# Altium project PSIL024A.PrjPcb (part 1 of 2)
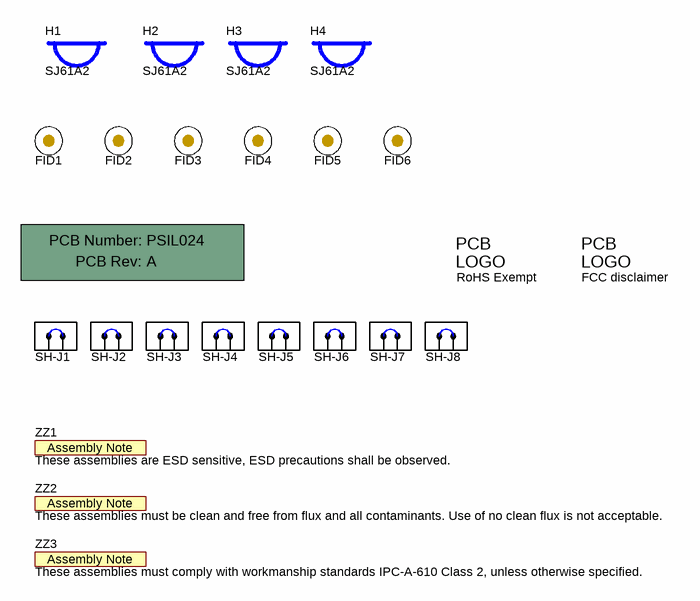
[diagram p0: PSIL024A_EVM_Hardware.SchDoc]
TID: TIDA-050023; TechSupport: http://www.ti.com/support; SCH_Rev: A; PRJ_Title: Class 6 Low Cost Flyback for PoE PD; PRJ_Number: PSIL024; PRJ_Engineer: D. Fernandez; PRJ_Customer: Public Release; PCB_Rev: A; PCB_Layout: D. Fernandez; Orderable: N/A; EVM_Orderable: N/A; CopyrightYear: 2018
4 sheets, 206 parts. Net scope: global (net labels, ports and power ports of the same name join across sheets).
Board file: PSIL024A_PCB.PcbDoc
Sheets:
  PSIL024A_EVM_Hardware.SchDoc
  PSIL024A_sch1.SchDoc
  PSIL024A_sch2.SchDoc
  PSIL024A_sch3.SchDoc

## Sheet PSIL024A_EVM_Hardware.SchDoc
size 431 x 279 mm; Date: Not shown in title block; ApprovedBy: Not shown in title block; CheckedBy: Not shown in title block; Author: Not shown in title block; CompanyName: Not shown in title block; Engineer: Not shown in title block; Organization: Not shown in title block; Address1: Not shown in title block; Address2: Not shown in title block; Address3: Not shown in title block; Address4: Not shown in title block; DocumentNumber: 1; Revision: Use project parameter SCH_Rev; SheetNumber: 4; SheetTotal: 4; PageSetup: Record=PageOptions¦CenterHorizontal=True¦CenterVertical=True¦PrintScale=1.00¦XCorrection=1.00¦YCorrection=1.00¦PrintKind=0¦BorderSize=5000000¦LeftOffset=0¦BottomOffset=0¦Orientation=2¦PaperLength=1000¦PaperWidth=1000¦Scale=100¦PaperSource=15¦PrintQuality=600¦MediaType=1¦DitherType=10¦PaperKind=Letter¦PrintScaleMode=1

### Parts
!PCB1  Printed Circuit Board  (value not drawn)  (mechanical)
FID1  Fiducial  [Fiducial10-20]  (value not drawn)
FID2  Fiducial  [Fiducial10-20]  (value not drawn)
FID3  Fiducial  [Fiducial10-20]  (value not drawn)
FID4  Fiducial  [Fiducial10-20]  (value not drawn)
FID5  Fiducial  [Fiducial10-20]  (value not drawn)
FID6  Fiducial  [Fiducial10-20]  (value not drawn)
H1  SJ61A2  [Bumpon_SJ61A2]
H2  SJ61A2  [Bumpon_SJ61A2]
H3  SJ61A2  [Bumpon_SJ61A2]
H4  SJ61A2  [Bumpon_SJ61A2]
Logo3  FCC disclaimer  [FCC_disclaimer]  (no BOM)
RoHS_Exempt  EU RoHS Exempt Logo  [EURoHS_Exempt_60mil]  (value not drawn)  (no BOM)
SH-J1  SPC02SYAN  [SPC02SYAN]  (value not drawn)
SH-J2  SPC02SYAN  [SPC02SYAN]  (value not drawn)
SH-J3  SPC02SYAN  [SPC02SYAN]  (value not drawn)
SH-J4  SPC02SYAN  [SPC02SYAN]  (value not drawn)
SH-J5  SPC02SYAN  [SPC02SYAN]  (value not drawn)
SH-J6  SPC02SYAN  [SPC02SYAN]  (value not drawn)
SH-J7  SPC02SYAN  [SPC02SYAN]  (value not drawn)
SH-J8  SPC02SYAN  [SPC02SYAN]  (value not drawn)
ZZ1  These assemblies are ESD sensitive, ESD precautions shall be observed.  [AssemblyNote]  (no BOM)
ZZ2  These assemblies must be clean and free from flux and all contaminants. Use of no clean flux is not acceptable.  [AssemblyNote]  (no BOM)
ZZ3  These assemblies must comply with workmanship standards IPC-A-610 Class 2, unless otherwise specified.  [AssemblyNote]  (no BOM)

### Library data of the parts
!PCB1 = PCB: Manufacturer: Any; PartNumber: PSIL024; SymbolCreator: a0412235
FID1-FID6 = Fiducial: Fiducial mark.  There is nothing to buy or mount.; SymbolCreator: codlsc
H1-H4 = SJ61A2: Bumpon, Hemisphere, 0.375 X 0.235, Black; Manufacturer: 3M; SymbolCreator: a0412235
Logo3 = FCC_disclaimer: SymbolCreator: codlsc
RoHS_Exempt = EURoHS_Exempt: SymbolCreator: a0412235
SH-J1-SH-J8 = SPC02SYAN: Shunt, 100mil, Flash Gold, Black; Manufacturer: Sullins Connector Solutions; Value: 1x2; Note: You can "mate" this to a header by matching the designator.  i.e. use SH-J3 for header J3; Green_Lifecycle: Active; Green_REACh: Passed
ZZ1-ZZ3 = AssemblyNote: SymbolCreator: codlsc

## Sheet PSIL024A_sch1.SchDoc
size 431 x 279 mm; Date: Not shown in title block; ApprovedBy: Not shown in title block; CheckedBy: Not shown in title block; Author: Not shown in title block; CompanyName: Not shown in title block; Engineer: Not shown in title block; Organization: Not shown in title block; Address1: Not shown in title block; Address2: Not shown in title block; Address3: Not shown in title block; Address4: Not shown in title block; DocumentNumber: 1; Revision: Use project parameter SCH_Rev; SheetNumber: 1; SheetTotal: 4; PageSetup: Record=PageOptions¦CenterHorizontal=True¦CenterVertical=True¦PrintScale=1.00¦XCorrection=1.00¦YCorrection=1.00¦PrintKind=0¦BorderSize=5000000¦LeftOffset=0¦BottomOffset=0¦Orientation=2¦PaperLength=1000¦PaperWidth=1000¦Scale=100¦PaperSource=15¦PrintQuality=600¦MediaType=1¦DitherType=10¦PaperKind=Letter¦PrintScaleMode=1
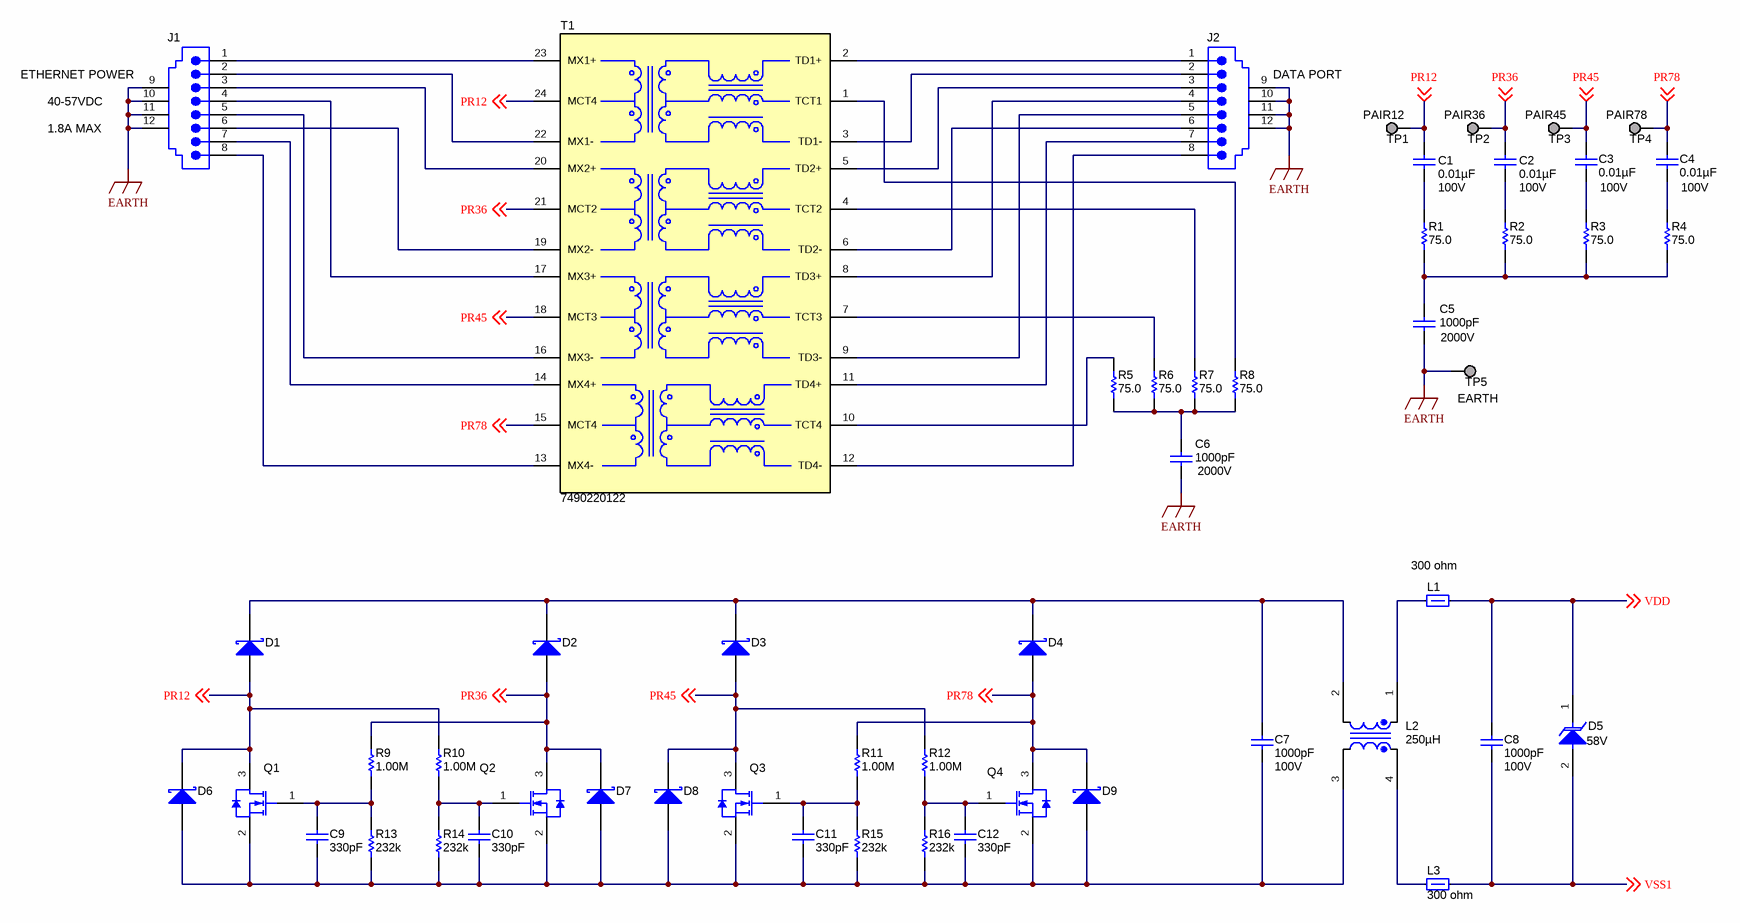
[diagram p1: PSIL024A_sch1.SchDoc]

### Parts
C1  ValueDisplayed: 0.01µF  Value2: 100V  [0603]  (hidden comment: C1608X7R2A103K)
C2  ValueDisplayed: 0.01µF  Value2: 100V  [0603]  (hidden comment: C1608X7R2A103K)
C3  ValueDisplayed: 0.01µF  Value2: 100V  [0603]  (hidden comment: C1608X7R2A103K)
C4  ValueDisplayed: 0.01µF  Value2: 100V  [0603]  (hidden comment: C1608X7R2A103K)
C5  ValueDisplayed: 1000pF  Value2: 2000V  [1808]  (hidden comment: GR442QR73D102KW01L)
C6  ValueDisplayed: 1000pF  Value2: 2000V  [1812_220]  (hidden comment: 1812GC102KAT1A)
C7  ValueDisplayed: 1000pF  Value2: 100V  [0603]  (hidden comment: C1608X7R2A102K)
C8  ValueDisplayed: 1000pF  Value2: 100V  [0603]  (hidden comment: C1608X7R2A102K)
C9  ValueDisplayed: 330pF  [0603]  (hidden comment: 885012006060)
C10  ValueDisplayed: 330pF  [0603]  (hidden comment: 885012006060)
C11  ValueDisplayed: 330pF  [0603]  (hidden comment: 885012006060)
C12  ValueDisplayed: 330pF  [0603]  (hidden comment: 885012006060)
D1  B2100-13-F  [SMB]  (value not drawn)
D2  B2100-13-F  [SMB]  (value not drawn)
D3  B2100-13-F  [SMB]  (value not drawn)
D4  B2100-13-F  [SMB]  (value not drawn)
D5  value 58V  [SMB]  (hidden comment: SMBJ58A-13-F)
D6  DNP  [SMB]  (value not drawn)
D7  DNP  [SMB]  (value not drawn)
D8  DNP  [SMB]  (value not drawn)
D9  DNP  [SMB]  (value not drawn)
J1  1-406541-1  [TEC_1-406541-1]  (value not drawn)
J2  1-406541-1  [TEC_1-406541-1]  (value not drawn)
L1  value 300 ohm  [WE-CBF_0603]
L2  ValueDisplayed: 250µH  [WE-SL5]  (hidden comment: 744272251)
L3  value 300 ohm  [WE-CBF_0603]
Q1  FDN8601  [SSOT-3]  (value not drawn)
Q2  FDN8601  [SSOT-3]  (value not drawn)
Q3  FDN8601  [SSOT-3]  (value not drawn)
Q4  FDN8601  [SSOT-3]  (value not drawn)
R1  value 75.0  [0603]  (hidden comment: CRCW060375R0FKEA)
R2  value 75.0  [0603]  (hidden comment: CRCW060375R0FKEA)
R3  value 75.0  [0603]  (hidden comment: CRCW060375R0FKEA)
R4  value 75.0  [0603]  (hidden comment: CRCW060375R0FKEA)
R5  value 75.0  [0603]  (hidden comment: CRCW060375R0FKEA)
R6  value 75.0  [0603]  (hidden comment: CRCW060375R0FKEA)
R7  value 75.0  [0603]  (hidden comment: CRCW060375R0FKEA)
R8  value 75.0  [0603]  (hidden comment: CRCW060375R0FKEA)
R9  ValueDisplayed: 1.00M  [0603]  (hidden comment: CRCW06031M00FKEA)
R10  ValueDisplayed: 1.00M  [0603]  (hidden comment: CRCW06031M00FKEA)
R11  ValueDisplayed: 1.00M  [0603]  (hidden comment: CRCW06031M00FKEA)
R12  ValueDisplayed: 1.00M  [0603]  (hidden comment: CRCW06031M00FKEA)
R13  ValueDisplayed: 232k  [0603]  (hidden comment: CRCW0603232KFKEA)
R14  ValueDisplayed: 232k  [0603]  (hidden comment: CRCW0603232KFKEA)
R15  ValueDisplayed: 232k  [0603]  (hidden comment: CRCW0603232KFKEA)
R16  ValueDisplayed: 232k  [0603]  (hidden comment: CRCW0603232KFKEA)
T1  7490220122  [Wurth_7490220122]
TP1  TESTPOINT  [Keystone_5019]  (value not drawn)
TP2  TESTPOINT  [Keystone_5019]  (value not drawn)
TP3  TESTPOINT  [Keystone_5019]  (value not drawn)
TP4  TESTPOINT  [Keystone_5019]  (value not drawn)
TP5  TESTPOINT  [Keystone_5019]  (value not drawn)

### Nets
EARTH: C5.2 C6.2 J1.9 J1.10 J1.11 J1.12 J2.9 J2.10 J2.11 J2.12 TP5.1
PR12: C1.1 D1.2(A) D6.1(K) Q1.3(D) R10.2 T1.24(MCT4) TP1.1 ; off-sheet PR12
PR36: C2.1 D2.2(A) D7.1(K) Q2.3(D) R9.2 T1.21(MCT2) TP2.1 ; off-sheet PR36
PR45: C3.1 D3.2(A) D8.1(K) Q3.3(D) R12.2 T1.18(MCT3) TP3.1 ; off-sheet PR45
PR78: C4.1 D4.2(A) D9.1(K) Q4.3(D) R11.2 T1.15(MCT4) TP4.1 ; off-sheet PR78
VDD: C8.1 D5.1(K) L1.2 ; off-sheet VDD
VSS1: C8.2 D5.2(A) L3.2 ; off-sheet VSS1
NetC1_2: C1.2 R1.2
NetC2_2: C2.2 R2.2
NetC3_2: C3.2 R3.2
NetC4_2: C4.2 R4.2
NetC5_1: C5.1 R1.1 R2.1 R3.1 R4.1
NetC6_1: C6.1 R5.2 R6.2 R7.2 R8.2
NetC7_1: C7.1 D1.1(K) D2.1(K) D3.1(K) D4.1(K) L2.2
NetC7_2: C7.2 C9.2 C10.2 C11.2 C12.2 D6.2(A) D7.2(A) D8.2(A) D9.2(A) L2.3 Q1.2(S) Q2.2(S) Q3.2(S) Q4.2(S) R13.1 R14.1 R15.1 R16.1
NetC9_1: C9.1 Q1.1(G) R9.1 R13.2
NetC10_1: C10.1 Q2.1(G) R10.1 R14.2
NetC11_1: C11.1 Q3.1(G) R11.1 R15.2
NetC12_1: C12.1 Q4.1(G) R12.1 R16.2
NetJ1_1: J1.1 T1.23(MX1+)
NetJ1_2: J1.2 T1.22(MX1-)
NetJ1_3: J1.3 T1.20(MX2+)
NetJ1_4: J1.4 T1.17(MX3+)
NetJ1_5: J1.5 T1.16(MX3-)
NetJ1_6: J1.6 T1.19(MX2-)
NetJ1_7: J1.7 T1.14(MX4+)
NetJ1_8: J1.8 T1.13(MX4-)
NetJ2_1: J2.1 T1.2(TD1+)
NetJ2_2: J2.2 T1.3(TD1-)
NetJ2_3: J2.3 T1.5(TD2+)
NetJ2_4: J2.4 T1.8(TD3+)
NetJ2_5: J2.5 T1.9(TD3-)
NetJ2_6: J2.6 T1.6(TD2-)
NetJ2_7: J2.7 T1.11(TD4+)
NetJ2_8: J2.8 T1.12(TD4-)
NetL1_1: L1.1 L2.1
NetL2_4: L2.4 L3.1
NetR5_1: R5.1 T1.10(TCT4)
NetR6_1: R6.1 T1.7(TCT3)
NetR7_1: R7.1 T1.4(TCT2)
NetR8_1: R8.1 T1.1(TCT1)

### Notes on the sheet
- ETHERNET POWER
- (near J2) DATA PORT
- 40-57VDC
- 1.8A MAX
- (near TP1) PAIR12
- (near TP2) PAIR36
- (near TP3) PAIR45
- (near TP4) PAIR78
- (near TP5) EARTH

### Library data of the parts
C1-C4 = C1608X7R2A103K: CAP, CERM, 0.01uF, 100V, +/-10%, X7R, 0603; Manufacturer: TDK; Polarized: N; CompType: Capacitor; U/M: EA; Cap_F: 0.00000001; Tolerance_%: 10; ESR_Ohm: 0.0661; Value1: 0.0661 ohm; VDC_V: 100; TaMin_C: -55; TaMax_C: 125
C5 = GR442QR73D102KW01L: CAP, CERM, 1000 pF, 2000 V, +/- 10%, X7R, 1808; Manufacturer: MuRata; Polarized: N; CompType: Capacitor; Value: 1000pF; U/M: EA; Cap_F: 0.000000001; Tolerance_%: 10; Value1: Unknown; VDC_V: 2000; TaMin_C: -55; TaMax_C: 125; AEC Category: Q200; SizeArea_mm2: 9; SizeAreaWB_mm2: 16.5; SizeX_mm: 4.5; SizeY_mm: 2; SizeZ_mm: 2.03
C6 = 1812GC102KAT1A: CAP, CERM, 1000 pF, 2000 V,+/- 10%, X7R, 1812; Manufacturer: AVX; Polarized: N; CompType: Capacitor; Value: 1000pF; U/M: EA; Cap_F: 0.000000001; Tolerance_%: 10; Value1: Unknown; VDC_V: 2000; TaMin_C: -55; TaMax_C: 125; Cap_Case: 1812; AEC Category: Q200; SizeArea_mm2: 14.4; SizeAreaWB_mm2: 23.1; SizeX_mm: 4.5; SizeY_mm: 3.2; SizeZ_mm: 2.2
C7 C8 = C1608X7R2A102K: CAP, CERM, 1000pF, 100V, +/-10%, X7R, 0603; Manufacturer: TDK; Polarized: N; CompType: Capacitor; U/M: EA; Cap_F: 0.000000001; Tolerance_%: 10; ESR_Ohm: 0.2494; Value1: 0.2494 ohm; VDC_V: 100; TaMin_C: -55; TaMax_C: 125
C9-C12 = 885012006060: CAP, CERM, 330 pF, 50 V, +/- 5%, C0G/NP0, 0603; Manufacturer: Wurth Elektronik; Polarized: N; CompType: Capacitor; Value: 330pF; U/M: EA; Cap_F: 0.00000000033; Tolerance_%: 5; Value1: Unknown; VDC_V: 50; Value2: 50V; TaMin_C: -55; TaMax_C: 125; AEC Category: Q200
D1-D4 D6-D9 = B2100-13-F: Diode, Schottky, 100 V, 2 A, SMB; Manufacturer: Diodes Inc.; Value: 100V; U/M: EA; Vf_V: 0.79; Value1: 2A; Value2: 0.79V; Io_A: 2; Vr_V: 100; TJmax_C: 150; RJC_CperW: 15; AEC Category: Q101
D5 = SMBJ58A-13-F: Diode, TVS, Uni, 58V, 600W, SMB; Manufacturer: Diodes Inc.; U/M: EA; Power_W: 5; Vr_V: 58; Value1: 5W
J1 J2 = 1-406541-1: RJ-45, No LED, tab up, R/A, TH; Manufacturer: TE Connectivity; SymbolCreator: x0208326; CompType: Connector; ContactFinish: Gold
L1 L3 = 742792641: Ferrite Bead, 300 ohm @ 100 MHz, 2 A, 0603; Manufacturer: Wurth Elektronik; Imax_A: 2; DCR_ohm: 0.15; Value1: 0.15 ohm; Value2: 2A; ZTyp@100MHz_Ohm: 300
L2 = 744272251: Coupled inductor, 250 µH,  A, 0.035 ohm, SMD; Manufacturer: Wurth Elektronik; SymbolCreator: a0412235; Value: 250uH; Ind_H: 250.0E-6; DCR_ohm: 0.035
Q1-Q4 = FDN8601: MOSFET, N-CH, 100V, 2.7A, SSOT-3; Manufacturer: Fairchild Semiconductor; Alternate Manufacturer: None; U/M: EA; ChType: N; VdsMax_V: 100; Value1: ? ohm; Rdson45_Ohm: 0; Value2: 3 nC; QgTyp_nC: 3; Vgs_V: 20; IdsMax_A: 2.7
R1-R8 = CRCW060375R0FKEA: RES, 75.0 ohm, 1%, 0.1W, 0603; Manufacturer: Vishay-Dale; CompType: Resistor; Res_ohm: 75; Value_Code: 75R0; Tolerance_%: 1; Power_W: 0.1; TempCo: 100 ppm/C; EIA_Code: E96; U/M: EA
R9-R12 = CRCW06031M00FKEA: RES, 1.00 M, 1%, 0.1 W, 0603; Manufacturer: Vishay-Dale; CompType: Resistor; Value: 1.00Meg; Res_ohm: 1000000; Value_Code: 1M00; Tolerance_%: 1; Power_W: 0.1; Value2: 0.1W; VDC_V: 75; TempCo: 100 ppm/C; EIA_Code: E96; U/M: EA; AEC Category: Q200
R13-R16 = CRCW0603232KFKEA: RES, 232 k, 1%, 0.1 W, 0603; Manufacturer: Vishay-Dale; CompType: Resistor; Value: 232k; Res_ohm: 232000; Tolerance_%: 1; Power_W: 0.1; Value2: 0.1W; VDC_V: 75; TempCo: 100 ppm/C; EIA_Code: E96; U/M: EA; AEC Category: Q200
T1 = 7490220122: Transformer, 350 uH, SMT; Manufacturer: Wurth Elektronik; SymbolCreator: Altium; Value: 350 uH; U/M: EA
TP1-TP5 = 5019: Test Point, Miniature, SMT; Manufacturer: Keystone; CompType: Test Point Loop; U/M: EA

## Sheet PSIL024A_sch2.SchDoc
size 431 x 279 mm; Date: Not shown in title block; ApprovedBy: Not shown in title block; CheckedBy: Not shown in title block; Author: Not shown in title block; CompanyName: Not shown in title block; Engineer: Not shown in title block; Organization: Not shown in title block; Address1: Not shown in title block; Address2: Not shown in title block; Address3: Not shown in title block; Address4: Not shown in title block; DocumentNumber: 1; Revision: Use project parameter SCH_Rev; SheetNumber: 2; SheetTotal: 4; PageSetup: Record=PageOptions¦CenterHorizontal=True¦CenterVertical=True¦PrintScale=1.00¦XCorrection=1.00¦YCorrection=1.00¦PrintKind=0¦BorderSize=5000000¦LeftOffset=0¦BottomOffset=0¦Orientation=2¦PaperLength=1000¦PaperWidth=1000¦Scale=100¦PaperSource=15¦PrintQuality=600¦MediaType=1¦DitherType=10¦PaperKind=Letter¦PrintScaleMode=1
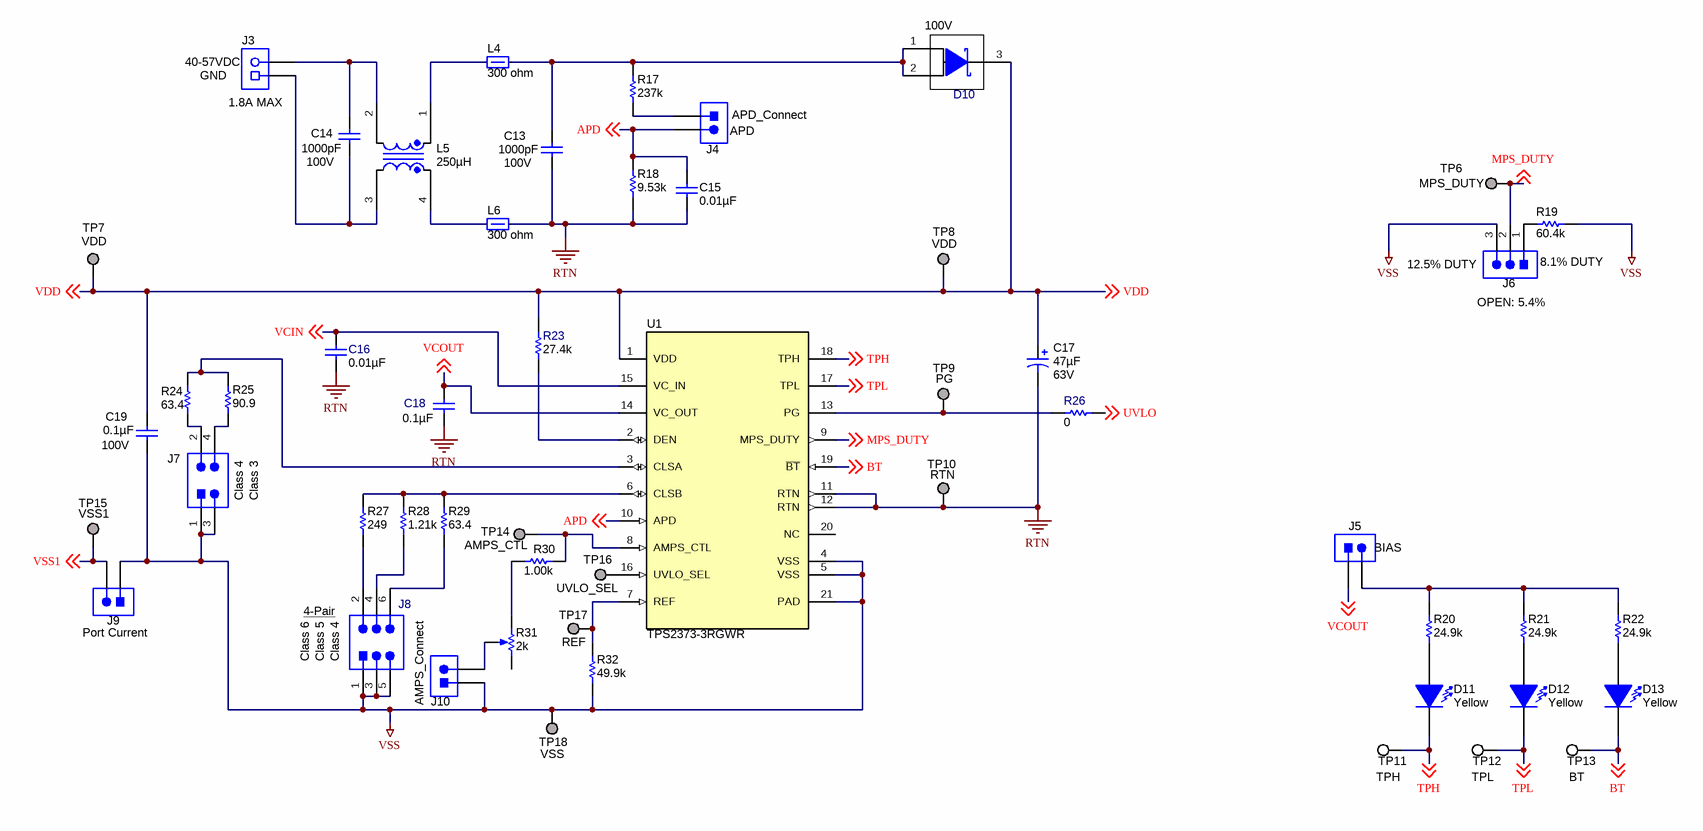
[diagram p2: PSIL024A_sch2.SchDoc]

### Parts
C13  ValueDisplayed: 1000pF  Value2: 100V  [0603L]  (hidden comment: C1608X7R2A102K)
C14  ValueDisplayed: 1000pF  Value2: 100V  [0603L]  (hidden comment: C1608X7R2A102K)
C15  ValueDisplayed: 0.01µF  [0603L]  (hidden comment: C1608X7R1H103K)
C16  ValueDisplayed: 0.01µF  [0603]  (hidden comment: GRM188R61H103KA01D)
C17  ValueDisplayed: 47µF  Value2: 63V  [SM_RADIAL_F]  (hidden comment: EEE-FK1J470P)
C18  ValueDisplayed: 0.1µF  [0603]  (hidden comment: 06033D104KAT2A)
C19  ValueDisplayed: 0.1µF  Value2: 100V  [0805_HV]  (hidden comment: C0805C104K1RACTU)
D10  100V  [PowerDI5]
D11  Yellow  [WL-SMCW_YELLOW]
D12  Yellow  [WL-SMCW_YELLOW]
D13  Yellow  [WL-SMCW_YELLOW]
J3  39357-0002  [Molex_39357-0002]  (value not drawn)
J4  87898-0204  [Molex_87898-0204]  (value not drawn)
J5  87898-0204  [Molex_87898-0204]  (value not drawn)
J6  TSM-103-01-L-SV  [Samtec_TSM-103-01-X-SV]  (value not drawn)
J7  15-91-2040  [Molex_15-91-2040]  (value not drawn)
J8  TSM-103-01-L-DV  [Samtec_TSM-103-01-x-DV]  (value not drawn)
J9  Port Current  [Molex_87898-0204]
J10  AMPS_Connect  [Molex_87898-0204]
L4  value 300 ohm  [WE-CBF_0603]
L5  ValueDisplayed: 250µH  [WE-SL5]  (hidden comment: 744272251)
L6  value 300 ohm  [WE-CBF_0603]
R17  value 237k  [0603L]  (hidden comment: CRCW0603237KFKEA)
R18  ValueDisplayed: 9.53k  [0603]  (hidden comment: CRCW06039K53FKEA)
R19  ValueDisplayed: 60.4k  [0603]  (hidden comment: CRCW060360K4FKEA)
R20  ValueDisplayed: 24.9k  [0603]  (hidden comment: CRCW060324K9FKEA)
R21  ValueDisplayed: 24.9k  [0603]  (hidden comment: CRCW060324K9FKEA)
R22  ValueDisplayed: 24.9k  [0603]  (hidden comment: CRCW060324K9FKEA)
R23  ValueDisplayed: 27.4k  [0603]  (hidden comment: RC0603FR-0727K4L)
R24  value 63.4  [0603]  (hidden comment: CRCW060363R4FKEA)
R25  ValueDisplayed: 90.9  [0603]  (hidden comment: CRCW060390R9FKEA)
R26  ValueDisplayed: 0  [0603L]  (hidden comment: CRCW06030000Z0EA)
R27  ValueDisplayed: 249  [0603]  (hidden comment: CRCW0603249RFKEA)
R28  ValueDisplayed: 1.21k  [0603]  (hidden comment: CRCW06031K21FKEA)
R29  value 63.4  [0603]  (hidden comment: CRCW060363R4FKEA)
R30  ValueDisplayed: 1.00k  [2010]  (hidden comment: CRCW20101K00FKEF)
R31  value 2k  [BOURNS_3386P]  (hidden comment: 3386P-1-202LF)
R32  ValueDisplayed: 49.9k  [0603]  (hidden comment: CRCW060349K9FKEA)
TP6  TESTPOINT  [Keystone_5019]  (value not drawn)
TP7  VDD  [Keystone_5019]
TP8  VDD  [Keystone_5019]
TP9  PG  [Keystone_5019]
TP10  RTN  [Keystone_5019]
TP11  5015  [Testpoint_Keystone_Miniature]  (value not drawn)
TP12  5015  [Testpoint_Keystone_Miniature]  (value not drawn)
TP13  5015  [Testpoint_Keystone_Miniature]  (value not drawn)
TP14  AMPS_CTL  [Keystone_5019]
TP15  VSS1  [Keystone_5019]
TP16  UVLO_SEL  [Keystone_5019]
TP17  REF  [Keystone_5019]
TP18  VSS  [Keystone_5019]
U1  TPS2373-3RGWR  [RGW0020B]

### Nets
RTN: C13.2 C15.1 C16.2 C17.2(-) C18.2 L6.2 R18.1 TP10.1 U1.11(RTN) U1.12(RTN)
VSS: C19.2 J6.3 J7.1 J7.3 J8.1 J8.3 J8.5 J9.1 J10.1 R19.2 R32.2 TP18.1 U1.4(VSS) U1.5(VSS) U1.21(PAD)
APD: C15.2 J4.2 R18.2 U1.10(APD) ; off-sheet APD
BT: D13.1(K) TP13.1 U1.19(~{BT}) ; off-sheet BT
MPS_DUTY: J6.2 TP6.1 U1.9(MPS_DUTY) ; off-sheet MPS_DUTY
TPH: D11.1(K) TP11.1 U1.18(TPH) ; off-sheet TPH
TPL: D12.1(K) TP12.1 U1.17(TPL) ; off-sheet TPL
UVLO: R26.2 ; off-sheet UVLO
VCIN: C16.1 U1.15(VC_IN) ; off-sheet VCIN
VCOUT: C18.1 J5.1 U1.14(VC_OUT) ; off-sheet VCOUT
VDD: C17.1(+) C19.1 D10.3(K) R23.2 TP7.1 TP8.1 U1.1(VDD) ; off-sheet VDD
VSS1: J9.2 TP15.1 ; off-sheet VSS1
NetC13_1: C13.1 D10.1(A) D10.2(A) L4.2 R17.2
NetC14_1: C14.1 J3.2 L5.2
NetC14_2: C14.2 J3.1 L5.3
NetD11_2: D11.2(A) R20.1
NetD12_2: D12.2(A) R21.1
NetD13_2: D13.2(A) R22.1
NetJ4_1: J4.1 R17.1
NetJ5_2: J5.2 R20.2 R21.2 R22.2
NetJ6_1: J6.1 R19.1
NetJ7_2: J7.2 R24.1
NetJ7_4: J7.4 R25.1
NetJ8_2: J8.2 R27.1
NetJ8_4: J8.4 R28.1
NetJ8_6: J8.6 R29.1
NetJ10_2: J10.2 R31.2(WIPER)
NetL4_1: L4.1 L5.1
NetL5_4: L5.4 L6.1
NetR23_1: R23.1 U1.2(DEN)
NetR24_2: R24.2 R25.2 U1.3(CLSA)
NetR26_1: R26.1 TP9.1 U1.13(PG)
NetR27_2: R27.2 R28.2 R29.2 U1.6(CLSB)
NetR30_1: R30.1 R31.1(CCW)
NetR30_2: R30.2 TP14.1 U1.8(AMPS_CTL)
NetR32_1: R32.1 TP17.1 U1.7(REF)
NetTP16_1: TP16.1 U1.16(UVLO_SEL)

Not connected (* = marked no-connect by the designer): R31 3(CW); U1 20(NC)

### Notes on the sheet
- (near J3) GND
- (near J3) 1.8A MAX
- (near J3) 40-57VDC
- (near J4) APD
- (near J4) APD_Connect
- (near TP6) MPS_DUTY
- (near J6) 12.5% DUTY
- (near J6) OPEN: 5.4%
- 8.1% DUTY
- (near J7) Class 4
- Class 3
- (near J5) BIAS
- (near J8) Class 6
- (near J8) Class 5
- (near J8) 4-Pair
- (near J8) Class 4
- (near TP11) TPH
- (near TP12) TPL
- (near TP13) BT

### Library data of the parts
C13 C14 = C1608X7R2A102K: CAP, CERM, 1000pF, 100V, +/-10%, X7R, 0603; Manufacturer: TDK; Polarized: N; CompType: Capacitor; U/M: EA; Cap_F: 0.000000001; Tolerance_%: 10; ESR_Ohm: 0.2494; Value1: 0.2494 ohm; VDC_V: 100; TaMin_C: -55; TaMax_C: 125; Cap_Case: 0603
C15 = C1608X7R1H103K: CAP, CERM, 0.01uF, 50V, +/-10%, X7R, 0603; Manufacturer: TDK; Polarized: N; CompType: Capacitor; U/M: EA; Cap_F: 0.00000001; Tolerance_%: 10; ESR_Ohm: 0.0539; Value1: 0.0539 ohm; VDC_V: 50; TaMin_C: -55; TaMax_C: 125; Cap_Case: 0603
C16 = GRM188R61H103KA01D: CAP, CERM, 0.01 µF, 50 V, +/- 10%, X5R, 0603; Manufacturer: MuRata; Polarized: N; CompType: Capacitor; Value: 0.01uF; U/M: EA; Cap_F: 0.00000001; Tolerance_%: 10; Value1: Unknown; VDC_V: 50; Value2: 50V; TaMin_C: -55; TaMax_C: 85; AEC Category: Q200
C17 = EEE-FK1J470P: CAP, AL, 47 µF, 63 V, +/- 20%, 0.65 ohm, SMD; Manufacturer: Panasonic; Polarized: Y; CompType: Capacitor; Value: 47uF; U/M: EA; Cap_F: 0.000047; Tolerance_%: 20; VDC_V: 63; ESR_ohm: 0.65; IRMS_A: 0.25; TaMin_C: -55; TaMax_C: 105; Cap_Case: F; AEC Category: Q200
C18 = 06033D104KAT2A: CAP, CERM, 0.1 µF, 25 V, +/- 10%, X5R, 0603; Manufacturer: AVX; Polarized: N; CompType: Capacitor; Value: 0.1uF; U/M: EA; Cap_F: 0.0000001; Tolerance_%: 10; ESR_ohm: 0.048; Value1: 0.048 ohm; VDC_V: 25; Value2: 25V; IRMS_A: 0.53; TaMin_C: -55; TaMax_C: 85; AEC Category: Q200
C19 = C0805C104K1RACTU: CAP, CERM, 0.1 µF, 100 V, +/- 10%, X7R, 0805; Manufacturer: Kemet; Polarized: N; CompType: Capacitor; Value: 0.1uF; U/M: EA; Cap_F: 0.0000001; Tolerance_%: 10; ESR_ohm: 0.064; Value1: 0.064 ohm; VDC_V: 100; IRMS_A: 1.64; TaMin_C: -55; TaMax_C: 125; Cap_Case: 0805; AEC Category: Q200
D10 = PDS5100-13: Diode, Schottky, 100 V, 5 A, PowerDI5; Manufacturer: Diodes Inc.; U/M: EA; Vf_V: 0.79; Value1: 5A; Value2: 0.79V; Io_A: 5; Vr_V: 100; TJmax_C: 150; AEC Category: Q101
D11-D13 = 150060YS75000: LED, Yellow, SMD; Manufacturer: Wurth Elektronik; Type: AlInGaP; Vf_V: 2; Value2: 2V; Io_A: 0.02; Value1: W; U/M: EA
J3 = 39357-0002: Terminal Block, 3.5 mm, 2x1, Tin, TH; Manufacturer: Molex; SymbolCreator: a0412235
J4 J5 J9 J10 = 87898-0204: Header, 2.54 mm, 2x1, Gold, R/A, SMT; Manufacturer: Molex; SymbolCreator: a0412235; Pitch_mm: 2.54; Gender: Male; Shrouded: N; Row_Count: 1
J6 = TSM-103-01-L-SV: Header, 100mil, 3x1, Gold, SMT; Manufacturer: Samtec; SymbolCreator: a0799628; U/M: EA
J7 = 15-91-2040: Header, 100mil, 2x2, Tin, SMT; Manufacturer: Molex; SymbolCreator: a0412235
J8 = TSM-103-01-L-DV: Header, 2.54mm, 3x2, Gold, SMT; Manufacturer: Samtec; SymbolCreator: a0412235; Pitch_mm: 2.54; Gender: Male; Shrouded: N; Row_Count: 2; Current_A: 4.9; Voltage_V: 475; Cert_CSA: Y; Green_Lifecycle: Active; Green_REACh: Passed
L4 L6 = 742792641: as L1 on sheet PSIL024A_sch1
L5 = 744272251: as L2 on sheet PSIL024A_sch1
R17 = CRCW0603237KFKEA: RES, 237k ohm, 1%, 0.1W, 0603; Manufacturer: Vishay-Dale; CompType: Resistor; Res_ohm: 237000; Tolerance_%: 1; Power_W: 0.1; VDC_V: 75; TempCo: 100 ppm/C; EIA_Code: E96; U/M: EA
R18 = CRCW06039K53FKEA: RES, 9.53 k, 1%, 0.1 W, 0603; Manufacturer: Vishay-Dale; CompType: Resistor; Value: 9.53k; Res_ohm: 9530; Value_Code: 9k53; Tolerance_%: 1; Power_W: 0.1; Value2: 0.1W; VDC_V: 75; TempCo: 100 ppm/C; EIA_Code: E96; U/M: EA; SizeArea_mm2: 1.28; SizeX_mm: 1.6; SizeY_mm: 0.8; AEC Category: Q200
R19 = CMP-0022532-4: RES, 60.4 k, 1%, 0.1 W, AEC-Q200 Grade 0, 0603; Manufacturer: Vishay-Dale; Power_W: 100mW; TempCo: 100 ppm/C; Value_Code: 60k4; Value: 60.4k; EIA_Code: E96; SizeX_mm: 1.6; SizeY_mm: 0.8; SizeZ_mm: 1; Value2: 0.1W; SizeArea_mm2: 1.28; AEC Qualified: Y; VDC_V: 75V; AEC Category: Q200; AEC Grade: 0
R20-R22 = CRCW060324K9FKEA: RES, 24.9 k, 1%, 0.1 W, 0603; Manufacturer: Vishay-Dale; CompType: Resistor; Value: 24.9k; Res_ohm: 24900; Value_Code: 24k9; Tolerance_%: 1; Power_W: 0.1; Value2: 0.1W; VDC_V: 75; TempCo: 100 ppm/C; EIA_Code: E96; U/M: EA; AEC Category: Q200; SizeArea_mm2: 1.28; SizeX_mm: 1.6; SizeY_mm: 0.8; Green_Lifecycle: Active; Green_REACh: Passed
R23 = RC0603FR-0727K4L: RES, 27.4 k, 1%, 0.1 W, 0603; Manufacturer: Yageo America; CompType: Resistor; Value: 27.4k; Res_ohm: 27400; Value_Code: 27k4; Tolerance_%: 1; Power_W: 0.1; Value2: 0.1W; VDC_V: 150; TempCo: 200 ppm/C; SizeArea_mm2: 1.28; SizeX_mm: 1.6; SizeY_mm: 0.8; EIA_Code: E96; U/M: EA; AEC Category: Q200
R24 R29 = CRCW060363R4FKEA: RES, 63.4 ohm, 1%, 0.1W, 0603; Manufacturer: Vishay-Dale; CompType: Resistor; Value_Code: 63R4; Tolerance_%: 1; Power_W: 0.1; VDC_V: 75; TempCo: 100 ppm/C; EIA_Code: E96; U/M: EA
R25 = CRCW060390R9FKEA: RES, 90.9, 1%, 0.1 W, 0603; Manufacturer: Vishay-Dale; CompType: Resistor; Value: 90.9; Value_Code: 90R9; Tolerance_%: 1; Power_W: 0.1; Value2: 0.1W; VDC_V: 75; TempCo: 100 ppm/C; EIA_Code: E96; U/M: EA; AEC Category: Q200
R26 = CRCW06030000Z0EA: RES, 0, 5%, 0.1 W, 0603; Manufacturer: Vishay-Dale; CompType: Resistor; Value: 0; Value_Code: 0000; Tolerance_%: 5; Power_W: 0.1; Value2: 0.1W; VDC_V: 75; TempCo: 200 ppm/C; EIA_Code: E24; U/M: EA; AEC Category: Q200
R27 = CRCW0603249RFKEA: RES, 249, 1%, 0.1 W, 0603; Manufacturer: Vishay-Dale; CompType: Resistor; Value: 249; Value_Code: 249R; Tolerance_%: 1; Power_W: 0.1; Value2: 0.1W; VDC_V: 75; TempCo: 100 ppm/C; EIA_Code: E96; U/M: EA; AEC Category: Q200; SizeArea_mm2: 1.28; SizeX_mm: 1.6; SizeY_mm: 0.8
R28 = CRCW06031K21FKEA: RES, 1.21 k, 1%, 0.1 W, 0603; Manufacturer: Vishay-Dale; CompType: Resistor; Value: 1.21k; Res_ohm: 1210; Value_Code: 1k21; Tolerance_%: 1; Power_W: 0.1; Value2: 0.1W; VDC_V: 75; TempCo: 100 ppm/C; EIA_Code: E96; U/M: EA; AEC Category: Q200; SizeArea_mm2: 1.28; SizeX_mm: 1.6; SizeY_mm: 0.8
R30 = CRCW20101K00FKEF: RES, 1.00 k, 1%, 0.75 W, 2010; Manufacturer: Vishay-Dale; CompType: Resistor; Value: 1.00k; Res_ohm: 1000; Value_Code: 1k00; Tolerance_%: 1; Power_W: 0.75; Value2: 0.75W; VDC_V: 400; TempCo: 100 ppm/C; EIA_Code: E96; U/M: EA; AEC Category: Q200
R31 = 3386P-1-202LF: TRIMMER, 2k ohm, 0.5W, TH; Manufacturer: Bourns; Sim Note: Enter the Resistance value and the set point into parameter fields.; SymbolCreator: a0412235
R32 = CRCW060349K9FKEA: RES, 49.9 k, 1%, 0.1 W, 0603; Manufacturer: Vishay-Dale; CompType: Resistor; Value: 49.9k; Res_ohm: 49900; Value_Code: 49k9; Tolerance_%: 1; Power_W: 0.1; Value2: 0.1W; VDC_V: 75; TempCo: 100 ppm/C; EIA_Code: E96; U/M: EA; AEC Category: Q200
TP6-TP10 TP14-TP18 = 5019: as TP1 on sheet PSIL024A_sch1
TP11-TP13 = 5015: Test Point, Miniature, SMT; Manufacturer: Keystone; CompType: Test Point Loop; U/M: EA
U1 = CMP-0013754-2: High-Power PoE PD Interface with Advanced Startup, RGW0020B (VQFN-20); Manufacturer: Texas Instruments; Alternate PartNumber: TPS2373-3RGWT; SizeX_mm: 5; CompType: IC; SizeZ_mm: 1; SizeArea_mm2: 25; SizeAreaWB_mm2: 49; U/M: EA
